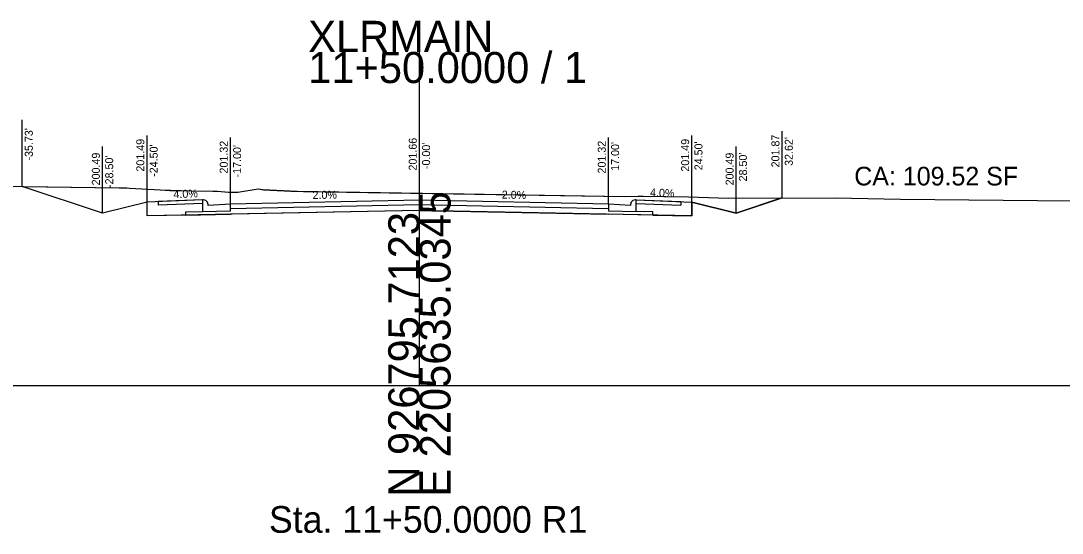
# Model space of a CAD drawing. Extents: x -26 to 303, y -13 to 1528.
# Drawn here: x 114.2 to 207.8, y 986.7 to 1032.8 of the extents above; entities that cross this region are included whole.
import ezdxf

# ---------------------------------------------------------------- set-up
doc = ezdxf.new("R2010")
doc.units = 0
for name, color, linetype in [('CONST_DCH', 7, 'Continuous'), ('CONST_LV3', 7, 'Continuous'), ('Draft_XS_Text', 7, 'Continuous'), ('DTM_TEMP_DROP', 7, 'Continuous'), ('DTM_X_BOUNDARY', 7, 'Continuous'), ('SLOPE_STAKES_FILL', 7, 'Continuous'), ('XS_CELL', 7, 'Continuous'), ('XS_M_SHAPES_EARTHWORK', 7, 'Continuous'), ('XS_P_ASPHALT', 7, 'Continuous'), ('XS_P_CONCRETE', 7, 'Continuous'), ('XS_P_GROUND', 7, 'Continuous'), ('XS_P_SHOULDER', 7, 'Continuous'), ('XS_P_SUBGRADE_GRANULAR', 7, 'Continuous'), ('XS_P_SUBGRADE_GRANULAR_B', 7, 'Continuous'), ('XS_P_TX_CLEARZONE', 7, 'Continuous'), ('XS_P_TX_FS_BS', 7, 'Continuous'), ('XS_SHEET_EW_TX_AREA', 7, 'Continuous')]:
    doc.layers.add(name, color=color, linetype=linetype)

msp = doc.modelspace()

# ---------------------------------------------------------------- linework, layer by layer
at = {"layer": 'CONST_LV3'}
for points in [[(129, 1015.324), (129, 1015.615), (130.5, 1015.645)], [(171, 1015.323), (171, 1015.615), (169.5, 1015.645)]]:
    msp.add_lwpolyline(points, dxfattribs=at)
at = {"layer": 'DTM_X_BOUNDARY'}
msp.add_lwpolyline([(112.267, 1017.936), (122.99, 1017.775), (123.692, 1017.765), (123.926, 1017.761), (126.682, 1017.596), (127.561, 1017.55), (131.416, 1017.488), (131.834, 1017.482), (132.823, 1017.403), (132.847, 1017.402), (133.675, 1017.389), (135.504, 1017.678), (135.825, 1017.615), (135.99, 1017.613), (138.422, 1017.474), (139.581, 1017.456), (168.477, 1017.011), (169.683, 1017.031), (170.163, 1017.024), (174.211, 1016.962), (177.796, 1016.855), (187.407, 1016.882), (193.282, 1016.772), (288.692, 1015.826)], dxfattribs=at)
at = {"layer": 'XS_CELL'}
for p, q in [((150, 1000), (150, 1030)), ((0, 1000), (150, 1000)), ((150, 1000), (300, 1000))]:
    msp.add_line(p, q, dxfattribs=at)
at = {"layer": 'XS_M_SHAPES_EARTHWORK'}
msp.add_lwpolyline([(149.982, 1015.743), (125.501, 1015.253), (125.5, 1016.495), (121.5, 1015.495), (114.268, 1017.906), (122.99, 1017.775), (123.926, 1017.761), (126.682, 1017.596), (129.489, 1017.519), (131.416, 1017.488), (131.834, 1017.482), (132.847, 1017.402), (133.675, 1017.389), (135.504, 1017.678), (135.907, 1017.614), (139.001, 1017.465), (154.029, 1017.234), (168.477, 1017.011), (169.683, 1017.031), (174.211, 1016.962), (177.796, 1016.855), (182.602, 1016.869), (178.5, 1015.495), (174.5, 1016.495), (174.499, 1015.253)], close=True, dxfattribs=at)
at = {"layer": 'XS_P_ASPHALT'}
for p, q in [((150, 1016.66), (133, 1016.32)), ((133, 1016.32), (133, 1016.32)), ((150.008, 1016.243), (133.008, 1015.903)), ((166.992, 1015.903), (149.992, 1016.243)), ((167, 1016.32), (150, 1016.66)), ((150, 1016.66), (150, 1016.66)), ((150, 1016.66), (150, 1016.66)), ((167, 1016.32), (167, 1016.32)), ((150, 1015.91), (150, 1015.91)), ((150, 1015.91), (150, 1015.91))]:
    msp.add_line(p, q, dxfattribs=at)
at = {"layer": 'XS_P_CONCRETE'}
for p, q in [((150, 1000), (150, 1030)), ((126.5, 1016.535), (126.5, 1016.205)), ((130.513, 1016.365), (126.5, 1016.205)), ((169.487, 1016.365), (173.5, 1016.205)), ((173.5, 1016.535), (173.5, 1016.205))]:
    msp.add_line(p, q, dxfattribs=at)
for points in [[(130.5, 1016.695), (126.5, 1016.535)], [(133, 1016.32), (131, 1016.195), (131, 1016.278), (131, 1016.278), (130.944, 1016.487), (130.944, 1016.487), (130.792, 1016.639), (130.792, 1016.639), (130.583, 1016.695), (130.583, 1016.695), (130.5, 1016.695), (130.5, 1016.695), (130.5, 1016.695), (130.5, 1015.645), (133, 1015.695), (133, 1015.695), (133, 1016.32), (133, 1016.32), (133, 1016.32)], [(167, 1016.32), (167, 1016.32), (167, 1016.32), (167, 1015.695), (167, 1015.695), (169.5, 1015.645), (169.5, 1016.695), (169.5, 1016.695), (169.417, 1016.695), (169.417, 1016.695), (169.417, 1016.695), (169.208, 1016.639), (169.208, 1016.639), (169.056, 1016.487), (169.056, 1016.487), (169, 1016.278), (169, 1016.278), (169, 1016.195), (167, 1016.32)], [(169.5, 1016.695), (173.5, 1016.535)]]:
    msp.add_lwpolyline(points, dxfattribs=at)
at = {"layer": 'XS_P_GROUND'}
for points in [[(121.5, 1015.495), (114.268, 1017.906)], [(125.5, 1016.495), (121.5, 1015.495)], [(174.5, 1016.495), (178.5, 1015.495)], [(178.5, 1015.495), (182.622, 1016.869)]]:
    msp.add_lwpolyline(points, dxfattribs=at)
at = {"layer": 'XS_P_SHOULDER'}
for points in [[(130.5, 1016.695), (125.5, 1016.495)], [(169.5, 1016.695), (174.5, 1016.495)]]:
    msp.add_lwpolyline(points, dxfattribs=at)
at = {"layer": 'XS_P_SUBGRADE_GRANULAR'}
for points in [[(128.982, 1015.323), (132.982, 1015.403)], [(149.982, 1015.743), (132.982, 1015.403)], [(149.982, 1015.743), (166.982, 1015.403)], [(170.982, 1015.323), (166.982, 1015.403)]]:
    msp.add_lwpolyline(points, dxfattribs=at)
at = {"layer": 'XS_P_SUBGRADE_GRANULAR_B'}
for points in [[(125.501, 1015.253), (125.5, 1016.495)], [(174.499, 1015.253), (174.5, 1016.495)], [(128.982, 1015.323), (125.501, 1015.253)], [(170.982, 1015.323), (174.499, 1015.253)]]:
    msp.add_lwpolyline(points, dxfattribs=at)
at = {"layer": 'XS_P_TX_CLEARZONE'}
for p, q in [((114.268, 1017.906), (114.268, 1023.906)), ((114.268, 1017.906), (114.268, 1023.906)), ((182.622, 1016.869), (182.622, 1022.869)), ((182.622, 1016.869), (182.622, 1022.869)), ((125.5, 1016.495), (125.5, 1022.495)), ((125.5, 1016.495), (125.5, 1022.495)), ((133, 1016.32), (133, 1022.32)), ((150, 1016.66), (150, 1022.66)), ((167, 1016.32), (167, 1022.32)), ((167, 1016.32), (167, 1022.32)), ((174.5, 1016.495), (174.5, 1022.495)), ((121.5, 1015.495), (121.5, 1021.495)), ((121.5, 1015.495), (121.5, 1021.495)), ((178.5, 1015.495), (178.5, 1021.495))]:
    msp.add_line(p, q, dxfattribs=at)

# ---------------------------------------------------------------- texts
at = {"layer": 'CONST_DCH'}
for p in [(132.996, 1016.314), (149.996, 1016.654), (166.996, 1016.314)]:
    msp.add_text('X', height=0.012, dxfattribs=at).set_placement(p)
at = {"layer": 'Draft_XS_Text'}
msp.add_text('Sta. 11+50.0000 R1', height=2.4, dxfattribs=at).set_placement((136.47, 986.75))
at = {"layer": 'DTM_TEMP_DROP'}
for p in [(121.496, 1015.489), (178.496, 1015.489)]:
    msp.add_text('X', height=0.012, dxfattribs=at).set_placement(p)
at = {"layer": 'SLOPE_STAKES_FILL'}
for p in [(125.496, 1016.489), (174.496, 1016.489)]:
    msp.add_text('X', height=0.012, dxfattribs=at).set_placement(p)
at = {"layer": 'XS_CELL'}
for s, p in [('XLRMAIN', (140, 1030)), ('11+50.0000 / 1', (140, 1027.2))]:
    msp.add_text(s, height=2.8, dxfattribs=at).set_placement(p)
for s, p in [('E 2205635.0345', (152.8, 990)), ('N 926795.7123', (150, 990))]:
    msp.add_text(s, height=2.8, rotation=90, dxfattribs=at).set_placement(p)
at = {"layer": 'XS_P_CONCRETE'}
for p in [(114.264, 1017.9), (182.618, 1016.863)]:
    msp.add_text('X', height=0.012, dxfattribs=at).set_placement(p)
at = {"layer": 'XS_P_TX_CLEARZONE'}
for s, p in [("-35.73'", (115.228, 1020.234)), ('201.49', (125.26, 1019.237)), ('201.49', (125.26, 1019.237)), ('201.32', (132.76, 1019.067)), ('201.66', (149.76, 1019.334)), ('201.32', (166.76, 1019.067)), ('201.32', (166.76, 1019.067)), ("17.00'", (167.96, 1019.306)), ("17.00'", (167.96, 1019.306)), ('201.49', (174.26, 1019.237)), ("24.50'", (175.46, 1019.356)), ('201.87', (182.382, 1019.616)), ('201.87', (182.382, 1019.616)), ("32.62'", (183.582, 1019.752)), ("32.62'", (183.582, 1019.752)), ('200.49', (121.26, 1017.999)), ("-24.50'", (126.46, 1018.766)), ("-24.50'", (126.46, 1018.766)), ("-17.00'", (133.96, 1018.716)), ("-0.00'", (150.96, 1019.464)), ('200.49', (178.26, 1017.999)), ("28.50'", (179.46, 1018.356)), ("-28.50'", (122.46, 1017.766))]:
    msp.add_text(s, height=0.72, rotation=90, dxfattribs=at).set_placement(p)
at = {"layer": 'XS_P_TX_FS_BS'}
for s, rotation, p in [('4.0%', 2.33743, (127.891, 1016.839)), ('2.0%', 1.14576, (140.392, 1016.768)), ('2.0%', 358.85424, (157.404, 1016.812)), ('4.0%', 357.63463, (170.732, 1017.015))]:
    msp.add_text(s, height=0.72, rotation=rotation, dxfattribs=at).set_placement(p)
at = {"layer": 'XS_SHEET_EW_TX_AREA'}
msp.add_text('CA: 109.52 SF', height=1.68, dxfattribs=at).set_placement((189.111, 1017.992))

doc.saveas('drawing.dxf')
